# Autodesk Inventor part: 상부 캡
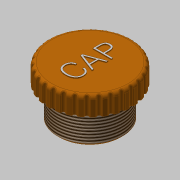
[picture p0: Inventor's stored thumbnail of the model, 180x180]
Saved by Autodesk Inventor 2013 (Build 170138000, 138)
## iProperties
Created: 2016-09
Part Number: 상부 캡
Material: ABS 플라스틱
Document SubType Name: Modeling
Designer: mduedu
Density: 1.493 g/cm^3
Mass: 32.6939 g
Surface Area: 67.9045 cm^2
Volume: 21.8981 cm^3
Author: mduedu
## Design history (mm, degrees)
sketch "스케치1"
  geometry: C1 r 22.5 at (0, 0); 1 further point
  constraints: 1 centre point, 1 coincident
  dimensions: "d0" = 45 diameter of C1
extrude "돌출1" new body sketch "스케치1" distance "d1" = 10; taper "d2" = 0 deg
fillet "모깎기1" dims "d11" = 2
sketch "스케치4"
  geometry: C1 r 17.5 at (0, 0); 1 further point
  constraints: 1 centre point, 1 coincident
  dimensions: "d14" = 35 diameter of C1
extrude "돌출4" join sketch "스케치4" distance "d15" = 17; taper "d16" = 0 deg
sketch "스케치5"
  geometry: C1 r 12.5 at (0, 0); 1 further point
  constraints: 1 centre point, 1 coincident
  dimensions: "d17" = 25 diameter of C1
extrude "돌출5" cut sketch "스케치5" distance "d18" = 10; taper "d19" = 0 deg
fillet "모깎기4" dims "d20" = 3
sketch "스케치6"
  geometry: L1 (0, 22.5)-(0, -22.5) reference; L2 (0, 17.5)-(-1, 17.5); L3 (-1, 17.5)-(-1, 16.5); L4 (-1, 16.5)-(0, 16.5); L5 (0, 16.5)-(0, 17.5); L6 (0, 17.5)-(-17, 17.5) reference; L7 (-20.4, 0)-(3.4, 0) reference; 1 further point
  constraints: 8 end point, 2 parallel, 1 collinear, 1 horizontal, 1 perpendicular, 1 point on line
  dimensions: "d26" = 1 distance of L2.start L2.end; "d28" = 1 distance of L2.end L3.end
revolve "회전1" sketch "스케치6" stored, may be unused: angle "d29" = 90 deg
feature "스레드1" dims "d21" = 10, "d22" = 0
chamfer "모따기1" distance "d23" = 1; stored, may be unused: second distance "d24" = 2, angle "d25" = 45 deg
chamfer "모따기2" distance "d30" = 1; stored, may be unused: second distance "d31" = 2, angle "d32" = 45 deg
sketch "스케치7"
  geometry: C1 r 1 at (0, 22.5); 2 further points
  constraints: 2 vertical alignment, 1 centre point, 1 other
  dimensions: "d33" = 2 diameter of C1
extrude "돌출6" cut sketch "스케치7" stored distance "d35" = 10; taper "d36" = 0 deg
fillet "모깎기5" dims "d37" = 0.5
sketch "스케치8"
  geometry: 2 further points
  constraints: 1 coincident, 1 other
feature "엠보싱1" sketch "스케치8" dims "d0" = 45, "d41" = 0.5, "d42" = 0
node "솔리드1"
pattern_circular "원형 패턴1" dims angle "d39" = 360 deg
